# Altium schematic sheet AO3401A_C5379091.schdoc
size 127 x 101 mm
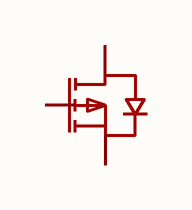
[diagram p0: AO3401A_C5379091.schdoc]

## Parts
Q?  ao3401a_c5379091  [SOT-23-3_L2.9-W1.6-P1.90-LS2.8-BR]  (value not drawn)

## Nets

Not connected (* = marked no-connect by the designer): Q? 1(G) 2(S) 3(D)

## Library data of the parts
Q? = ao3401a_c5379091: 数量:1个P沟道;漏源电压(Vdss):30V;连续漏极电流(Id):4A;导通电阻(RDS(on)):51mΩ@10V;耗散功率(Pd):1.56W;阈值电压(Vgs(th)):900mV;; Manufacturer: MSKSEMI(美森科); AddInBom: yes; ModelId: 89cb27a44ab2466697082bb9fd73a7d0; ModelName: SOT-23-3L_L2.9-W1.6-H1.1-LS2.8-P0.95; ModelTransform: 114.173,110.236,0,90,0,0,0,0,0; Number: 1个P沟道; Drain to Source Voltage: 30V; Current - Continuous Drain(Id): 4A; Pd - Power Dissipation: 1.56W; Gate Threshold Voltage (Vgs(th)): 900mV; Gate Charge(Qg): 8nC@4.5V; Input Capacitance(Ciss): 810pF; Reverse Transfer Capacitance (Crss@Vds): 50pF; Output Capacitance(Coss): 85pF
